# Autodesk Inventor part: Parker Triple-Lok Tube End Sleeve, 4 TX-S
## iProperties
Shininess: 20.0
Length Units: 11272
Angle Units: 11279
Time Units: 11290
Mass Units: 11286
Length Display Precision: 3
Angle Display Precision: 2
Created: 2001-05
Part Number: Parker Triple-Lok Tube End Sleeve, 4 TX-S
Document SubType Name: Modeling
Designer: jhagarty
Material: Stainless Steel, Austenitic
Description: Parker Triple-Lok Tube End Sleeve, 4 TX-S
Density: 0.0
Volumn: 0.0
Area: 0.0
PropertySet Name: Model Information
Control State: 0
Master: False
Checked Out: False
Last Check In Date: 2003-09-27
Last Check In By: Charles Bliss
Author: jhagarty
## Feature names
1. Revolution2
